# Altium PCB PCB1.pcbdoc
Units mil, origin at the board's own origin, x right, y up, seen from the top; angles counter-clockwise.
Board outline 4595.5 x 2047.9 mil, 2 copper layers (Top Layer, Bottom Layer), stack 62.2 mil thick; 88 components, 69 nets, 319 pads, 425 vias.
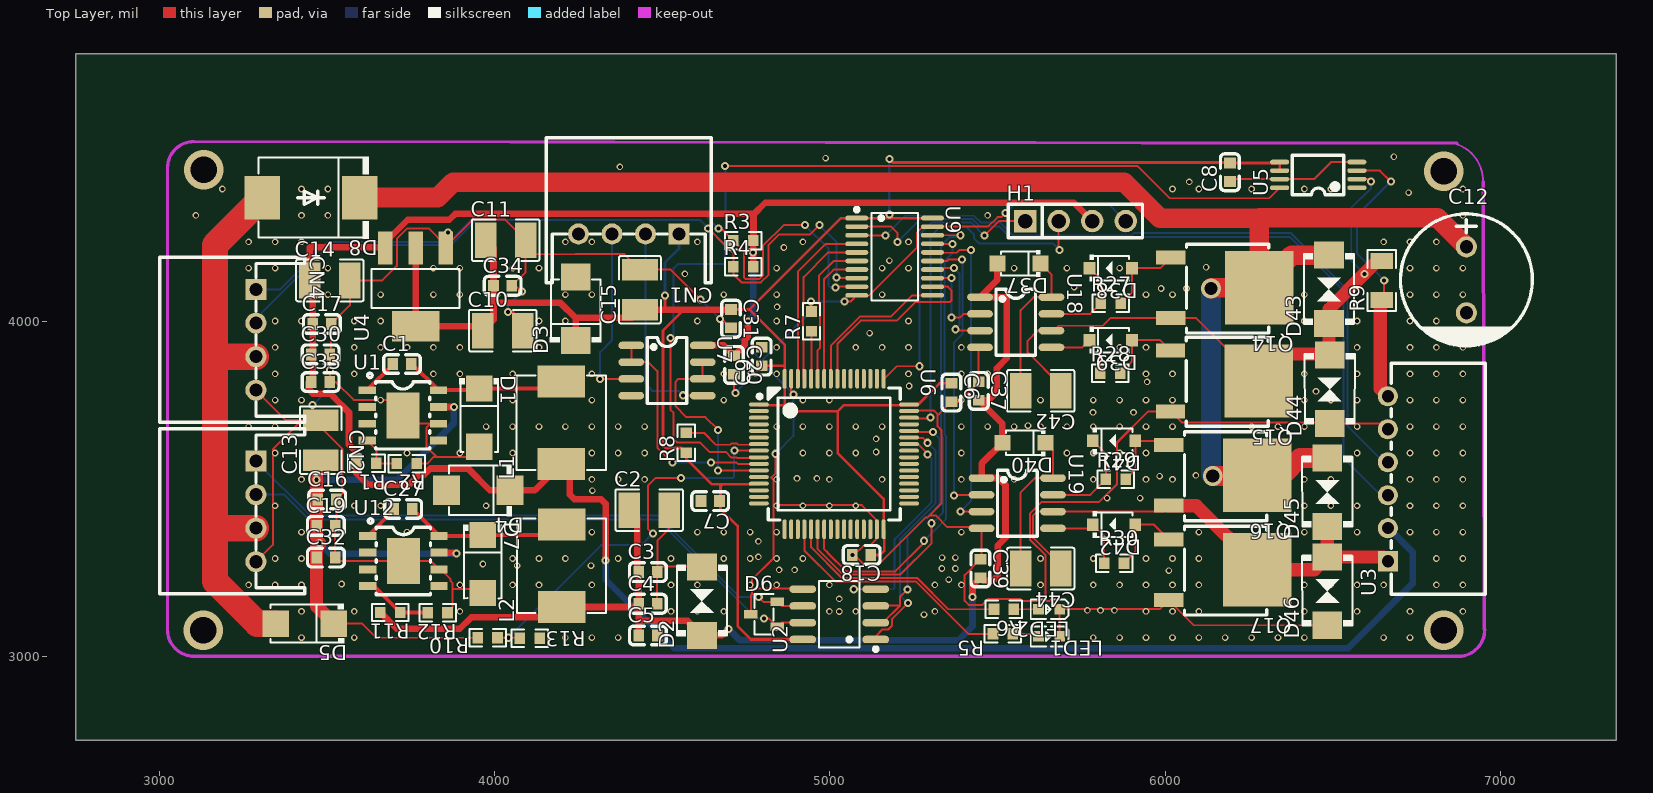
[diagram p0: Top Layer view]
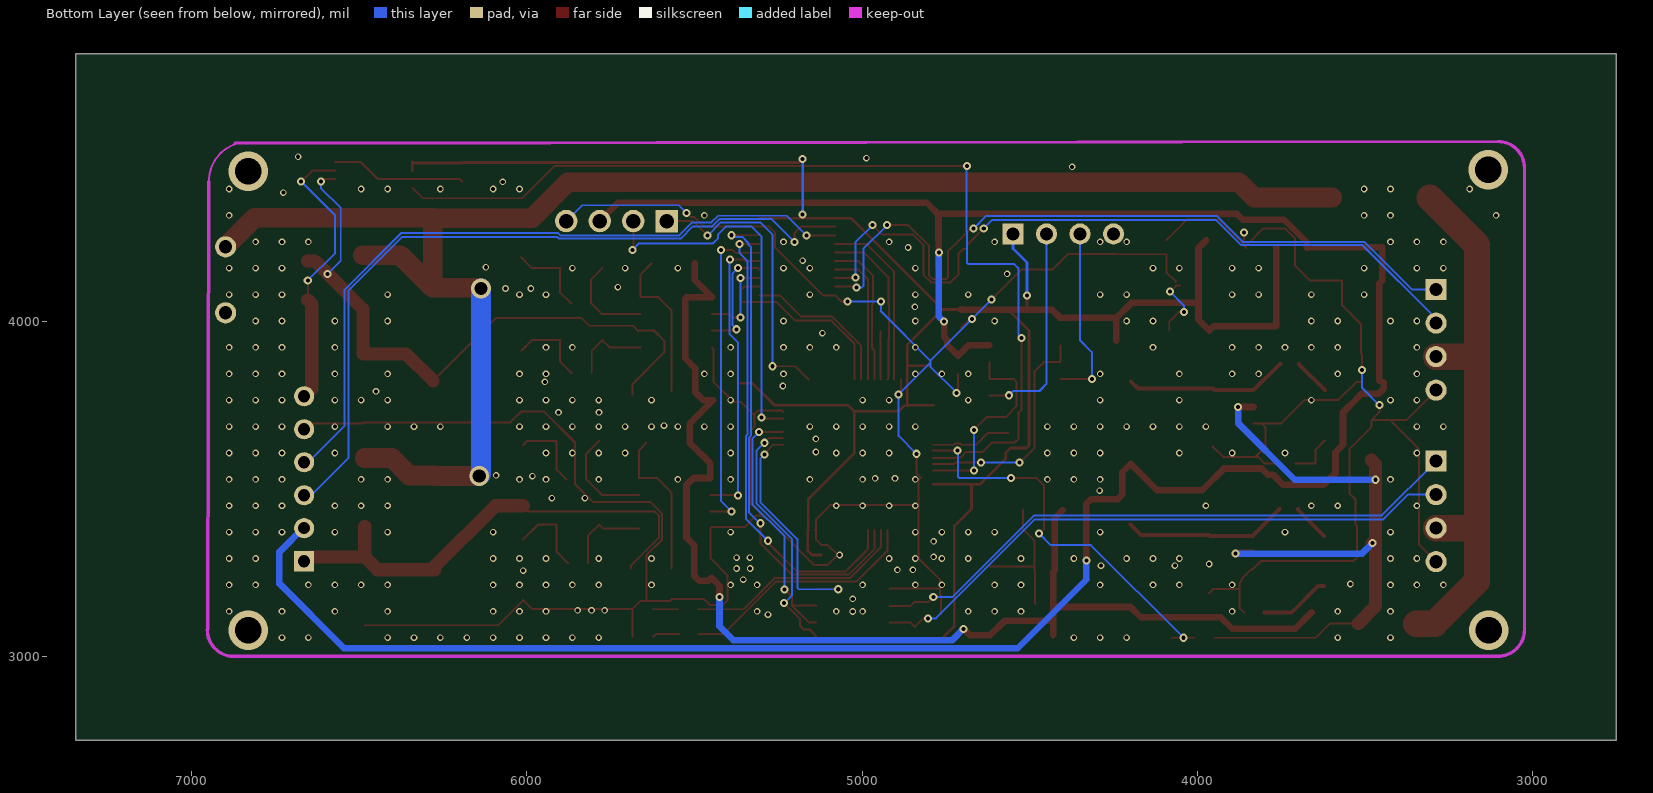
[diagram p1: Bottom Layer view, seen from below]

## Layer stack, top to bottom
Top Solder Mask Layer: solder mask 0.4, Dk 3.3
Top Layer: signal copper 1.4
Dielectric1: surface 59.4, FR4, Dk 4.5
Bottom Layer: signal copper 1.4
Bottom Solder Mask Layer: solder mask 0.4, Dk 3.3

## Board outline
7345.5,2750 2750,2750 2750,4797.9 7345.5,4797.9

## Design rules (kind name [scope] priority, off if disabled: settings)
BoardOutlineClearance copperThickness1oz [All] p0: genericclearance=10 ignorepadtopadclearanceinfootprint=FALSE except(0: Arc-SplitContinuation Track-SplitContinuation SMDPad-SplitContinuation THPad-SplitContinuation Via-SplitContinuation Fill-SplitContinuation Poly-SplitContinuation Region-SplitContinuation Text-SplitContinuation)
BoardOutlineClearance copperThickness2oz [All] p0: genericclearance=10 ignorepadtopadclearanceinfootprint=FALSE except(0: Arc-SplitContinuation Track-SplitContinuation SMDPad-SplitContinuation THPad-SplitContinuation Via-SplitContinuation Fill-SplitContinuation Poly-SplitContinuation Region-SplitContinuation Text-SplitContinuation)
BoardOutlineClearance otherClearance [All] p0: genericclearance=10 ignorepadtopadclearanceinfootprint=FALSE except(0: Arc-SplitContinuation Track-SplitContinuation SMDPad-SplitContinuation THPad-SplitContinuation Via-SplitContinuation Fill-SplitContinuation Poly-SplitContinuation Region-SplitContinuation Text-SplitContinuation)
Clearance copperThickness1oz [All] p1: gap=7 ignorepadtopadclearanceinfootprint=FALSE
Clearance copperThickness2oz [All] p1: gap=7 ignorepadtopadclearanceinfootprint=FALSE
Clearance otherClearance [All] p1: gap=7 ignorepadtopadclearanceinfootprint=FALSE
DiffPairsRouting differentialPair [All] p1: maxuncoupledlength=10 minlimit=6 maxlimit=Infinity mostfreqgap=6 toplayer_minwidth=5 toplayer_prefwidth=10 toplayer_maxwidth=100 bottomlayer_minwidth=5 bottomlayer_prefwidth=10 bottomlayer_maxwidth=100
PasteMaskExpansion pasteMaskExpansion [All] p1: expansion=0
PlaneConnect innerPlane [All] p1: planeconnectstyle=Direct reliefexpansion=20 reliefentries=4 reliefconductorwidth=10 reliefairgap=10
PolygonConnect copperRegion [All] p1: connectstyle=Direct reliefentries=4 reliefconductorwidth=10 polygonreliefangle="90 Angle" airgapwidth=10
RoutingVias viaSize [All] p1: viastyle="Through Hole" holewidth=12.0078 minholewidth=11.811 maxholewidth=248.0314 width=12.0078 minwidth=11.811 maxwidth=248.0314
SolderMaskExpansion solderMaskExpansion [IsVia] p1: useseparateexpansions=TRUE expansion=-1000 expansionbottom=-1000
SolderMaskExpansion solderMaskExpansion [All] p2: useseparateexpansions=TRUE expansion=2 expansionbottom=2
Width copperThickness1oz [All] p1: maxlimit=100 minlimit=5 preferedwidth=6
Width copperThickness2oz [All] p1: maxlimit=100 minlimit=8 preferedwidth=10
Width l24V [All] p1: maxlimit=100 minlimit=4 preferedwidth=39
Width i5V [All] p1: maxlimit=100 minlimit=5 preferedwidth=20
Width i3V [All] p1: maxlimit=100 minlimit=5 preferedwidth=8

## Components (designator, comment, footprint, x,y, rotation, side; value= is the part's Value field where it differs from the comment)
C1 "100nF" C0603#1 3723.3,3872.7 r0 top
C2 "10uF" C1210#1 4460.6,3436.7 r0 top
C3 "100nF" C0603#2 4456.7,3251.7 r0 top
C4 "100nF" C0603#2 4456.7,3157.2 r0 top
C5 "100nF" C0603#2 4456.7,3062.7 r0 top
C6 "100nF" C0603#1 5362.2,3787.1 r270 top
C7 "100nF" C0603#3 4642.7,3463.3 r180 top
C8 "100nF" C0603#3 6192.9,4444.6 r90 top
C9 "100nF" C0603#3 4796.3,3894.4 r90 top
C10 "10uF" C1210#1 4023.6,3972.1 r0 top
C11 "10uF" C1210#2 4032.2,4242 r0 top
C12 "470uF" CAP-TH_BD10.0-P5.00-D0.6-FD 6898.6,4123.7 r270 top
C13 "10uF" C1210#3 3480.3,3645.4 r90 top
C14 "10uF" C1210#3 3507.9,4121.7 r0 top
C15 "10uF" C1210#3 4433.1,4094.2 r90 top
C16 "100nF" C0603#2 3500,3468.2 r0 top
C17 "100nF" C0603#3 3484.3,3991.8 r0 top
C18 "100nF" C0603#1 5094.5,3302.8 r180 top
C19 "100nF" C0603#3 3496.1,3389.4 r0 top
C20 "100nF" C0603#1 4713.6,3869.8 r270 top
C27 "100nF" C0603#3 3726.7,3440 r0 top
C30 "100nF" C0603#1 3480.3,3901.3 r0 top
C31 "100nF" C0603#1 4704.7,4007.6 r270 top
C32 "100nF" C0603#3 3496.1,3295 r0 top
C33 "100nF" C0603#1 3480.3,3818.6 r0 top
C34 "100nF" C0603#1 4023.6,4106 r0 top
C37 "100nF" C0603#3 5443.7,3792.3 r270 top
C39 "100nF" C0603#3 5448.7,3262.3 r270 top
C42 "10uF" C1210#3 5628.7,3792.3 r180 top
C44 "10uF" C1210#3 5628.7,3262.3 r180 top
CN1 "2.54-4P WZ-D" CONN-TH_2.54-4P-WZ-D 4399.6,4260.5 r180 top
CN2 "2.54-4P WZ-D" CONN-TH_2.54-4P-WZ-D 3287.4,3432.8 r270 top
CN4 "2.54-4P WZ-D" CONN-TH_2.54-4P-WZ-D 3287.4,3944.6 r270 top
D1 "B340A-E3/61T" SMA_L4.3-W2.6-LS5.2-RD 3953.3,3712.7 r270 top
D2 "SMBJ36CA" SMB_L4.6-W3.6-LS5.4-BI#1 4618.1,3165 r90 top
D3 "SMBJ5.0A" SMB_L4.6-W3.6-LS5.4-RD 4241.1,4037.1 r90 top
D4 "SMBJ5.0A" SMB_L4.6-W3.6-LS5.4-RD 3950.8,3495.7 r180 top
D5 "B340A-E3/61T" SMA_L4.3-W2.6-LS5.2-RD 3433.1,3098.1 r180 top
D6 "SM712" SOT-23-3_L2.9-W1.3-P1.90-LS2.4-BR 4803.1,3125.7 r0 top
D7 "B340A-E3/61T" SMA_L4.3-W2.6-LS5.2-RD 3964.4,3275.8 r270 top
D8 "B560C" SMC_L6.9-W5.9-LS7.9-RD 3451.8,4368.8 r180 top
D37 "FR107W" SOD-123FL_L2.7-W1.8-LS3.8-RD 5563.7,4172.3 r180 top
D38 "1N4148W" SOD-123_L2.7-W1.6-LS3.7-FD 5837.7,4158.4 r180 top
D39 "1N4148W" SOD-123_L2.7-W1.6-LS3.7-FD 5837.7,3943.4 r180 top
D40 "FR107W" SOD-123FL_L2.7-W1.8-LS3.8-RD 5578.7,3637.3 r180 top
D41 "1N4148W" SOD-123_L2.7-W1.6-LS3.7-FD 5847.7,3643.4 r180 top
D42 "1N4148W" SOD-123_L2.7-W1.6-LS3.7-FD 5847.7,3393.4 r180 top
D43 "SMBJ36CA" SMB_L4.6-W3.6-LS5.4-BI#2 6488.7,4095.1 r90 top
D44 "SMBJ36CA" SMB_L4.6-W3.6-LS5.4-BI#2 6490.7,3797.1 r90 top
D45 "SMBJ36CA" SMB_L4.6-W3.6-LS5.4-BI#2 6483.7,3490.1 r90 top
D46 "SMBJ36CA" SMB_L4.6-W3.6-LS5.4-BI#2 6483.7,3195.1 r90 top
H1 "PZ254V-11-04P" HDR-TH_4P-P2.54-V-M 5732.3,4298.9 r0 top
L1 "22uH" IND-SMD_L7.0-W6.6_FXL0630 4198.3,3697.7 r90 top
L2 "22uH" IND-SMD_L7.0-W6.6_FXL0630 4199.4,3270.8 r90 top
LED1 "" LED_0603 5651.6,3059.7 r180 top
LED2 "" LED_0603 5651.6,3140.8 r180 top
Q14 "CMD100N08A" TO-252-3_L6.5-W5.8-P4.58-LS9.5-BR#1 6148.7,4100.1 r180 top
Q15 "CMD100N08A" TO-252-3_L6.5-W5.8-P4.58-LS9.5-BR#1 6147.7,3822 r180 top
Q16 "CMD100N08A" TO-252-3_L6.5-W5.8-P4.58-LS9.5-BR#2 6142.7,3540.3 r180 top
Q17 "CMD100N08A" TO-252-3_L6.5-W5.8-P4.58-LS9.5-BR#2 6142.7,3258.5 r180 top
R1 "10K" R0603#1 3617.1,3576.5 r180 top
R2 "10K" R0603#2 3737.2,3575.5 r180 top
R3 "10K" R0603#1 4741.2,4240.8 r0 top
R4 "10K" R0603#1 4741.2,4163.1 r0 top
R5 "10K" R0603#3 5516,3067.5 r180 top
R6 "10K" R0603#1 5518.7,3140.8 r180 top
R7 "10kΩ" R0603#1 4944.9,3999.7 r90 top
R8 "10kΩ" R0603#1 4570.9,3637.5 r90 top
R9 "10mΩ" R1206 6645.7,4121.7 r90 top
R10 "10K" R0603#1 3978.3,3055.8 r180 top
R11 "10K" R0603#3 3688.4,3131.1 r180 top
R12 "10K" R0603#2 3829.4,3130.8 r180 top
R13 "10K" R0603#1 4104.3,3054.8 r180 top
R27 "10K" R0603#1 5837.7,4053.4 r0 top
R28 "10K" R0603#3 5835.9,3845.3 r0 top
R29 "10K" R0603#1 5852.7,3528.4 r0 top
R30 "10K" R0603#1 5847.7,3278.4 r0 top
U1 "TPS5430DDAR" ESOP-8_L4.9-W3.9-P1.27-LS6.0-TL-EP 3725.6,3719.3 r0 top
U2 "SP3485EEN(UMW)" SOP-8_L5.0-W4.0-P1.27-LS6.0-BL 5027.6,3125.7 r90 top
U3 "WAFER-XH254WZ-6A" CONN-TH_6P-P2.50_WAFER-XH254WZ-6A 6664.4,3530.2 r90 top
U4 "AMS1117-3.3" SOT-223-3_L6.5-W3.4-P2.30-LS7.0-BR 3763.8,4102 r90 top
U5 "INA240A1PWR" TSSOP-8_L4.4-W3.0-P0.65-LS6.4-BL 6456.7,4436.7 r90 top
U6 "STM32F103RCT6" LQFP-64_L10.0-W10.0-P0.50-LS12.0-BL 5011.8,3604 r270 top
U7 "LM258DR" SOIC-8_L5.0-W4.0-P1.27-LS6.0-BL 4513.8,3853 r270 top
U9 "74HC245PW,118" TSSOP-20_L6.5-W4.4-P0.65-LS6.4-BL 5192.9,4192.6 r270 top
U12 "TPS5430DDAR" ESOP-8_L4.9-W3.9-P1.27-LS6.0-TL-EP 3727.5,3284.8 r0 top
U18 "EG2104S" SOIC-8_L5.0-W4.0-P1.27-LS6.0-BL 5554.1,3996.9 r270 top
U19 "EG2104S" SOIC-8_L5.0-W4.0-P1.27-LS6.0-BL 5558.7,3457.3 r270 top

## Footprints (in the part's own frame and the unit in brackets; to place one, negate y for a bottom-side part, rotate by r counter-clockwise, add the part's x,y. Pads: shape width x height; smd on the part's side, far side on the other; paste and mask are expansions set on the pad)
C0603#1 [mil]
  rect 31.5x35.4 smd: 1(-27.5,0) 2(27.6,0)
  silkscreen extent -55,-28 55,28
C0603#2 [mil]
  rect 31.5x35.4 smd: 1(-27.6,0) 2(27.6,0)
  silkscreen extent -55,-28 55,28
C0603#3 [mil]
  rect 31.5x35.4 smd: 1(-27.6,0) 2(27.5,0)
  silkscreen extent -55,-28 55,28
C1210#1 [mil]
  rect 64.4x106.3 smd paste-3937 mask+2: 1(-59.7,0) 2(59.8,0)
  silkscreen extent -101,-62 101,62
C1210#2 [mil]
  rect 64.4x106.3 smd paste-3937 mask+2: 1(-59.7,0) 2(59.7,0)
  silkscreen extent -101,-62 101,62
C1210#3 [mil]
  rect 64.4x106.3 smd paste-3937 mask+2: 1(-59.8,0) 2(59.7,0)
  silkscreen extent -101,-62 101,62
CAP-TH_BD10.0-P5.00-D0.6-FD [mil]
  round 63 hole 39.4 paste+0 mask+2: 1(-98.4,0) 2(98.4,0)
  silkscreen extent -197,-197 200,197
CONN-TH_2.54-4P-WZ-D [mil]
  rect 63x63 hole 39.4 paste+0 mask+2: 1(-150,0)
  round 63 hole 39.4 paste+0 mask+2: 2(-50,0) 3(50,0) 4(150,0)
  silkscreen extent -246,-287 246,146
CONN-TH_6P-P2.50_WAFER-XH254WZ-6A [mil]
  rect 60x60 hole 36: 1(-246.1,0)
  round 60 hole 36: 2(-147.6,0) 3(-49.2,0) 4(49.2,0) 5(147.6,0) 6(246.1,0)
  silkscreen extent -345,-290 345,-10
ESOP-8_L4.9-W3.9-P1.27-LS6.0-TL-EP [mm]
  rect 1.3x0.599 smd: 1(-2.7,1.905) 2(-2.7,0.635) 3(-2.7,-0.635) 4(-2.7,-1.905) 5(2.7,-1.905) 6(2.7,-0.635) 7(2.7,0.635) 8(2.7,1.905)
  rect 2.499x3.5 smd: 9(0,0)
  silkscreen extent -2.67,-2.55 2.05,3.2
HDR-TH_4P-P2.54-V-M [mil]
  rect 66.9x66.9 hole 43.3: 1(-150,0)
  round 66.9 hole 43.3: 2(-50,0) 3(50,0) 4(150,0)
  silkscreen extent -200,-50 200,50
IND-SMD_L7.0-W6.6_FXL0630 [mil]
  rect 95.4x142.5 smd: 1(123.1,0) 2(-123.2,0)
  silkscreen extent -141,-133 141,133
LED_0603 [mil]
  rect 31.5x31.5 smd paste+0 mask+2: 1(-33.5,-0.4) 2(29.5,-0.2)
  silkscreen extent -61,-30 53,30
LQFP-64_L10.0-W10.0-P0.50-LS12.0-BL [mil]
  oval 11.8x59.1 smd: 1(-147.7,-223.9) 2(-128,-223.9) 3(-108.3,-223.9) 4(-88.6,-223.9) 5(-68.9,-223.9) 6(-49.2,-223.9) 7(-29.5,-223.9) 8(-9.9,-223.9) 9(9.8,-223.9) 10(29.5,-223.9) 11(49.2,-223.9) 12(68.9,-223.9) 13(88.6,-223.9) 14(108.3,-223.9) 15(127.9,-223.9) 16(147.6,-223.9) 33(147.6,224) 34(127.9,224) 35(108.3,224) 36(88.6,224) 37(68.9,224) 38(49.2,224) 39(29.5,224) 40(9.8,224) 41(-9.9,224) 42(-29.5,224) 43(-49.2,224) 44(-68.9,224) 45(-88.6,224) 46(-108.3,224) 47(-128,224) 48(-147.7,224)
  oval 59.1x11.8 smd: 17(224.4,-147.2) 18(224.4,-127.5) 19(224.4,-107.8) 20(224.4,-88.1) 21(224.4,-68.4) 22(224.4,-48.7) 23(224.4,-29.1) 24(224.4,-9.4) 25(224.4,10.3) 26(224.4,30) 27(224.4,49.7) 28(224.4,69.4) 29(224.4,89.1) 30(224.4,108.7) 31(224.4,128.4) 32(224.4,148.1) 49(-224.4,148.1) 50(-224.4,128.4) 51(-224.4,108.7) 52(-224.4,89.1) 53(-224.4,69.4) 54(-224.4,49.7) 55(-224.4,30) 56(-224.4,10.3) 57(-224.4,-9.4) 58(-224.4,-29.1) 59(-224.4,-48.7) 60(-224.4,-68.4) 61(-224.4,-88.1) 62(-224.4,-107.8) 63(-224.4,-127.5) 64(-224.4,-147.2)
  silkscreen extent -197,-228 197,197
R0603#1 [mil]
  rect 31.8x34 smd paste-3937 mask+2: 1(-29.7,0) 2(29.6,0)
  silkscreen extent -55,-26 54,26
R0603#2 [mil]
  rect 31.8x34 smd paste-3937 mask+2: 1(-29.7,0) 2(29.7,0)
  silkscreen extent -54,-26 54,26
R0603#3 [mil]
  rect 31.8x34 smd paste-3937 mask+2: 1(-29.6,0) 2(29.7,0)
  silkscreen extent -54,-26 55,26
R1206 [mil]
  rect 47.5x67 smd paste-3937 mask+2: 1(-58.2,0) 2(58.3,0)
  silkscreen extent -91,-43 91,43
SMA_L4.3-W2.6-LS5.2-RD [mil]
  rect 78.7x78.7 smd: 1(-86.6,0) 2(86.6,0)
  silkscreen extent -117,-59 102,59
SMB_L4.6-W3.6-LS5.4-BI#1 [mil]
  rect 80.6x88.2 smd: 1(-102,0) 2(102.1,0)
  silkscreen extent -105,-75 108,75
SMB_L4.6-W3.6-LS5.4-BI#2 [mil]
  rect 80.6x88.2 smd: 1(-102,0) 2(102,0)
  silkscreen extent -105,-75 108,75
SMB_L4.6-W3.6-LS5.4-RD [mil]
  rect 80.6x88.2 smd: 1(-95,0) 2(95,0)
  silkscreen extent -100,-77 88,77
SMC_L6.9-W5.9-LS7.9-RD [mil]
  rect 106.3x129.9 smd: 1(-145.1,0) 2(145.2,0)
  silkscreen extent -172,-122 157,122
SOD-123_L2.7-W1.6-LS3.7-FD [mil]
  rect 34.6x37.8 smd: 1(-63.4,0) 2(63.4,0)
  silkscreen extent -54,-39 63,40
SOD-123FL_L2.7-W1.8-LS3.8-RD [mil]
  rect 47.2x47.2 smd: 1(-64.4,0) 2(64.3,0)
  silkscreen extent -63,-40 54,39
SOIC-8_L5.0-W4.0-P1.27-LS6.0-BL [mil]
  oval 22.4x76.8 smd: 1(-75,-106.5) 2(-25,-106.5) 3(25,-106.5) 4(75,-106.5) 5(75,106.5) 6(25,106.5) 7(-25,106.5) 8(-75,106.5)
  silkscreen extent -99,-59 98,59
SOP-8_L5.0-W4.0-P1.27-LS6.0-BL [mil]
  oval 22.6x80.1 smd: 1(-75,-108.9) 2(-25,-108.9) 3(25,-108.9) 4(75,-108.9) 5(75,109) 6(25,109) 7(-25,109) 8(-75,109)
  silkscreen extent -110,-115 99,60
SOT-23-3_L2.9-W1.3-P1.90-LS2.4-BR [mil]
  rect 39.4x25.6 smd: 1(39.4,-37.4) 2(39.4,37.4) 3(-39.3,0)
  silkscreen extent -28,-60 29,60
SOT-223-3_L6.5-W3.4-P2.30-LS7.0-BR [mil]
  rect 98.4x43.3 smd: 1(117,-90.5) 2(117,0) 3(117,90.6)
  rect 92.1x141.7 smd: 4(-116.9,0)
  silkscreen extent -62,-131 54,131
TO-252-3_L6.5-W5.8-P4.58-LS9.5-BR#1 [mil]
  rect 87.3x41.9 smd: 1(131.8,-90.5) 3(131.8,90.6)
  rect 204.9x218.6 smd: 2(-131.9,0)
  silkscreen extent -160,-130 85,135
TO-252-3_L6.5-W5.8-P4.58-LS9.5-BR#2 [mil]
  rect 87.3x41.9 smd: 1(131.8,-90.6) 3(131.8,90.5)
  rect 204.9x218.6 smd: 2(-131.9,0)
  silkscreen extent -160,-130 85,135
TSSOP-8_L4.4-W3.0-P0.65-LS6.4-BL [mil]
  oval 13.9x57.2 smd: 1(-38.4,-115.2) 2(-12.8,-115.2) 3(12.8,-115.2) 4(38.4,-115.2) 5(38.4,115.2) 6(12.8,115.2) 7(-12.8,115.2) 8(-38.4,115.2)
  silkscreen extent -59,-76 59,77
TSSOP-20_L6.5-W4.4-P0.65-LS6.4-BL [mil]
  oval 14.3x68.6 smd: 1(-115.2,-113) 2(-89.6,-113) 3(-64,-113) 4(-38.4,-113) 5(-12.8,-113) 6(12.8,-113) 7(38.4,-113) 8(64,-113) 9(89.6,-113) 10(115.2,-113) 11(115.2,113) 12(89.6,113) 13(64,113) 14(38.4,113) 15(12.8,113) 16(-12.8,113) 17(-38.4,113) 18(-64,113) 19(-89.6,113) 20(-115.2,113)
  silkscreen extent -146,-119 131,70

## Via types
v1: diameter 19.7, hole 11.8, Top Layer to Bottom Layer, 296 vias
v2: diameter 24, hole 12, Top Layer to Bottom Layer, 73 vias
v3: diameter 19.7, hole 12, Top Layer to Bottom Layer, 50 vias
v4: diameter 118.1, hole 78.7, Top Layer to Bottom Layer, 4 vias
v5: diameter 59.1, hole 39.4, Top Layer to Bottom Layer, 2 vias

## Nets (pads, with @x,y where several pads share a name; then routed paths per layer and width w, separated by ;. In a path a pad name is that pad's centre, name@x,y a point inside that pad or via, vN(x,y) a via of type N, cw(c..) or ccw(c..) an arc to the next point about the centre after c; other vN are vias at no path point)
3.3V: C6.1 C7.1 C8.2 C9.1 C10.1 C11.1 C15.1 C18.1 C31.1 C34.1 CN1.1 D3.1 R8.1 U2.8 U4.2 U4.4 U5.5 U5.6 U6.1 U6.13 U6.32 U6.48 U6.64 U9.1 U9.20 | length 6839.1
  Top Layer w7.9: 4506.7,4034.4 4507.9,4035.7 v2(4507.9,4077.4) ; 4564,4034.4 4502,3972.4 4502,3629.6 4509.8,3621.7 4557,3621.7 R8.1 4570.9,3590.2 4647.6,3513.5 4679.1,3513.5 ; C31.1 4759.8,4035.1 ; U6.13@4787.9,3513.5 4679.1,3513.5 ; U6.1@4787.9,3749.7 4863.1,3749.7 4864.6,3748.2 ; C9.1 4863.1,3866.8 4864.6,3868.4 ; U2.8 4764,3050.7 4724.4,3090.2 4724.4,3389.4 4673.2,3440.6 4673.2,3507.6 4679.1,3513.5 ; C18.1 5149.6,3302.8 5161.4,3314.6 5161.4,3376.1 5159.9,3377.6 5159.9,3469.7 5023.6,3606 5023.6,3732 ; v2(5177.2,4318.6) 5188,4307.8 ; v2(5177.2,4483.5) 5187.2,4473.5 6191.6,4473.5 C8.2 6338.5,4472.1 U5.5 U5.6 ; U9.20 5188,4307.8 ; C6.1 5326.8,3814.6 5261.8,3749.7 5235.8,3749.7 5041.3,3749.7 5023.6,3732 ; 4759.8,4035.1 5032.5,4307.8 U9.1 5188,4307.8 ; 4759.8,4035.1 4864.6,3930.3 4864.6,3868.4 ; 4864.6,3748.2 4865.1,3747.7 4874,3747.7 4889.8,3732 5023.6,3732 ; 4864.6,3748.2 U6.64 4864.6,3868.4
  Top Layer w19.7: U4.2 U4.4 3950.9,3985.1 C10.1 3996.1,4004.3 3996.1,4059.4 ; C11.1 3996.1,4218.4 C34.1 3996.1,4059.4 ; D3.1 4241.1,4010 ; C31.1 4704,4034.4 4564,4034.4 4506.7,4034.4 C15.1 4409.6,4011 4240.2,4011 4196.3,4054.8 4000.7,4054.8 3996.1,4059.4
  Bottom Layer w7.9: v2(4507.9,4077.4) 4507.9,4174.9 4549.6,4216.6 CN1.1 ; v2(5177.2,4318.6) v2(5177.2,4483.5)
12V: C2.1 C3.1 C4.1 C5.1 C37.2 C39.2 D2.1 D37.2 D40.2 L2.2 R11.2 U18.1 U19.1 | length 3686
  Top Layer w19.7: R11.2 3707.5,3082.4 3895.7,3082.4 3930.1,3116.8 4168.6,3116.8 L2.2 4419.6,3147.6 C4.1 ; C2.1 4425.2,3412.4 4425.2,3255.6 C3.1 C4.1 ; C5.1 4429.1,3114.6 ; v2(4696.8,3082.4) 4677.5,3063 D2.1 4575.1,3106 4437.8,3106 4429.1,3114.6 ; v2(5425.2,3176.9) 5425.2,3211.2 C39.2 5457.6,3225.9 5486.1,3225.9 5500,3239.8 5500,3330.4 5523.6,3354 5523.6,3511.5 5502.8,3532.3 U19.1 5452.2,3575.2 D40.2 5514.4,3694.1 C37.2 5473.7,3764.8 5498,3789.1 5498,3859.9 5527.6,3889.4 5527.6,4066.6 5522.2,4071.9 U18.1 5499.4,4123.7 D37.2 ; 4429.1,3114.6 C4.1
  Bottom Layer w19.7: v2(4696.8,3082.4) 4730.3,3048.9 5383.9,3048.9 5425.2,3090.2 v2(5425.2,3176.9)
24V: C13.1 C16.1 C19.1 C32.1 D5.1 R10.2 U1.7 U12.7 | length 2012.1
  Top Layer w5.9: D5.1 3604.3,3098.1 3646.7,3055.8 R10.2
  Top Layer w19.7: U1.7 3877.5,3744.3 v2(3878,3743.8) ; U12.7 3882.8,3309.8 v2(3885.8,3306.8)
  Top Layer w39.4: v2(3476.4,3338.3) v2@3478.5,3336.1 ; C13.1 3468.5,3573.8 v2(3468.5,3527.2) C19.1 C32.1 3468.5,3149.3 D5.1
  Bottom Layer w19.7: v2(3468.5,3527.2) 3708.7,3527.2 3878,3696.5 v2(3878,3743.8) ; v2(3476.4,3338.3) 3507.9,3306.8 v2(3885.8,3306.8)
24V-M: C12.1 D8.1 D43.2 D45.2 Q14.2 Q16.2 | length 4928.3
  Top Layer w59.1: D8.1 3829.7,4368.8 3876,4415 5877,4415 5984.9,4307.1 6280.6,4307.1 ; v5(6136.8,4098.1) 6138.8,4100.1 Q14.2 ; v5(6141.7,3538.1) 6272.3,3538.1 Q16.2 6350.7,3540.3 6402.5,3592.1 D45.2 ; D43.2 6377.6,4197.1 Q14.2 ; C12.1 6812,4308.7 6282.2,4308.7 6280.6,4307.1 ; Q14.2 6280.6,4307.1
  Bottom Layer w59.1: v5(6136.8,4098.1) 6136.8,3543 v5(6141.7,3538.1)
24V-P: CN2.3 CN4.3 D5.2 D8.2 | length 1681.6
  Top Layer w78.7: CN2.3 3287.2,3382.6 3165.1,3382.6 ; CN4.3 3165.1,3894.6 ; D8.2 3165.1,4227.2 3165.1,3894.6 ; D5.2 3291.1,3098.1 3165.1,3224.1 3165.1,3382.6 ; 3165.1,3382.6 3165.1,3894.6
$1N1: C1.1 U1.1 | length 110.1
  Top Layer w11.8: U1.1 3695.8,3870.7 C1.1
$1N2: C27.1 U12.1 | length 112.5
  Top Layer w11.8: U12.1 3699.1,3437.7 C27.1
$1N3: C1.2 D1.1 L1.1 U1.8 | length 490.9
  Top Layer w11.8: C1.2 3753.5,3872.7 U1.8 3948.3,3794.3 D1.1 4176.8,3799.3 L1.1
$1N4: C27.2 D7.1 L2.1 U12.8 | length 492.9
  Top Layer w11.8: C27.2 3833.8,3360.4 U12.8 3961.8,3359.8 D7.1 4167.9,3362.4 L2.1
$1N7: R1.1 R2.2 U1.4 | length 140.3
  Top Layer w5.9: U1.4 3646.8,3616.8 R1.1 3647.8,3575.5 R2.2
$1N8: R11.1 R12.2 U12.4 | length 211.3
  Top Layer w11.8: U12.4 3639.4,3209.8 R11.1 3799.4,3131.1 R12.2
$1N71: U6.57 U9.11 | length 464.5
  Top Layer w5.9: U6.57 5002.4,3927.3 5089.6,4014.4 5182.1,4014.4 5245.1,4077.4 U9.11
$1N72: U6.58 U9.7 | length 408.4
  Top Layer w5.9: U6.58@4982.7,3826.5 4982.7,4126.1 5010.8,4154.2 U9.7
$1N73: U6.59 U9.6 | length 444.4
  Top Layer w5.9: U6.59@4963.1,3826.5 4963.1,3913.5 4970.8,3921.3 4970.8,4048.9 4967.9,4051.8 4967.9,4136.6 5011.1,4179.8 U9.6
$1N74: U6.61 U9.5 | length 497.5
  Top Layer w5.9: U6.61@4923.7,3826.5 4921.3,3828.9 4921.3,3948.1 4918.9,3950.4 4918.9,4048.9 4921.3,4051.2 4921.3,4131.8 4994.8,4205.4 U9.5
$1N75: U6.62 U9.4 | length 532
  Top Layer w5.9: U6.62@4904,3826.5 4904,4148.3 4986.7,4231 U9.4
$1N90: C44.2 D40.1 U19.8 | length 455.5
  Top Layer w5.9: C44.2 5569,3489.9 5611.4,3532.3 U19.8 5665.2,3615.2 D40.1
$1N92: H1.1 U6.49 | length 881.4
  Top Layer w5.9: U6.49@5159.9,3826.5 5199.3,3865.8 v2(5267.7,3865.8) ; v2(5460.6,4255.6) 5503.9,4298.9 H1.1
  Bottom Layer w5.9: v2(5267.7,3865.8) 5267.7,4259.5 5303.1,4295 5421.3,4295 v2(5460.6,4255.6)
$1N93: H1.2 U6.46 | length 1126.4
  Top Layer w5.9: U6.46@5235.8,3710.3 5297.2,3710.3 v2(5299.2,3712.3) ; H1.2 5682.3,4215 v2(5685,4212.3)
  Bottom Layer w5.9: v2(5299.2,3712.3) 5299.2,4251.7 5330.7,4283.1 5405.5,4283.1 5429.1,4259.5 5429.1,4247.7 5444.9,4232 5665.4,4232 v2(5685,4212.3)
$1N120: D38.1 Q14.1 R27.2 | length 248.2
  Top Layer w5.9: R27.2 5901.1,4087.1 D38.1 5984.7,4158.4 Q14.1
$1N121: D41.1 Q16.1 R29.2 | length 231.9
  Top Layer w5.9: R29.2 5911.1,3557.1 D41.1 5998.4,3643.4 Q16.1
$1N122: D42.1 Q17.1 R30.2 | length 247.2
  Top Layer w5.9: R30.2 5911.1,3312.1 D42.1 5966.6,3393.4 Q17.1
$1N123: D39.1 Q15.1 R28.2 | length 240.4
  Top Layer w5.9: R28.2 5901.1,3880.8 D39.1 5985.1,3943.4 Q15.1
$1N124: D38.2 R27.1 U18.7 | length 279.4
  Top Layer w5.9: U18.7 5776.6,4021.9 R27.1 5808,4124.7 D38.2
$1N125: D39.2 R28.1 U18.5 | length 234
  Top Layer w5.9: U18.5 5752.8,3921.9 D39.2 5806.3,3911.4 R28.1
$1N126: D41.2 R29.1 U19.7 | length 308
  Top Layer w5.9: U19.7 5777,3482.3 R29.1 5823,3604.7 D41.2
$1N127: D42.2 R30.1 U19.5 | length 252.7
  Top Layer w5.9: U19.5 5773.2,3382.3 D42.2 5818,3359.7 R30.1
$1N128: C42.2 D37.1 U18.8 | length 462.4
  Top Layer w5.9: C42.2 5569,4033.3 5607.7,4071.9 U18.8 5660.6,4139.8 D37.1
$1N138: R8.2 U6.7 | length 242.1
  Top Layer w5.9: R8.2@4563,3666.9 4624.1,3666.9 4659.4,3631.6 4702.7,3631.6 4705.9,3634.8 4723.2,3634.8 4726.5,3631.6 U6.7@4787.9,3631.6
$1N139: R7.1 U6.60 | length 144.1
  Top Layer w5.9: U6.60@4943.4,3826.5 4944.9,3828 R7.1
$1N154: U6.30
$1N155: U6.29
$1N156: U6.28
$1N157: U6.27
$1N158: U6.26
$1N159: R6.2 U6.21 | length 674.2
  Top Layer w5.9: U6.21@4943.4,3377.6 4943.4,3325.7 5035.1,3234 5260,3234 5353.2,3140.8 R6.2
$1N160: R5.2 U6.20 | length 727.1
  Top Layer w5.9: U6.20@4923.7,3377.6 4923.7,3316.1 5015.7,3224.1 5255.9,3224.1 5412.5,3067.5 R5.2
$1N223: LED1.2 R5.1 | length 79.6
  Top Layer w5.9: R5.1 5614.4,3067.5 LED1.2
$1N227: LED2.2 R6.1 | length 73.8
  Top Layer w5.9: R6.1 5621.9,3140.8 LED2.2
$1N253: U6.17
$1N261: U6.56 U9.12 | length 589.1
  Top Layer w5.9: U6.56 5022.1,3932.2 5091.5,4001.7 5199.8,4001.7 5255.9,4057.8 5358.3,4057.8 5362.4,4061.9 5362.4,4092.2 5351.6,4103 U9.12
$1N270: CN1.3 U7.3 | length 541.4
  Top Layer w5.9: v2(4314,3827.4) 4406.7,3827.4 U7.3
  Bottom Layer w5.9: v2(4314,3827.4) 4314,3908.1 4349.6,3943.8 CN1.3
$1N271: CN1.2 U7.5 | length 632.8
  Top Layer w5.9: v2(4562,3779.2) 4619.1,3779.2 U7.5
  Bottom Layer w5.9: CN1.2 4449.6,3812.9 4470.5,3792 4549.2,3792 v2(4562,3779.2)
$1N277: R10.1 R13.2 U6.8 | length 1195.2
  Top Layer w5.9: R10.1 v2(4040.7,3055.8) 4073.7,3055.8 R13.2 ; v2(4471.5,3366.8) 4456.7,3381.6 4456.7,3509.8 4478.8,3531.9 v2(4556.1,3531.9) ; v2(4714.6,3613.9) U6.8
  Bottom Layer w5.9: v2(4040.7,3055.8) 4317.2,3332.4 4437,3332.4 v2(4471.5,3366.8) ; v2(4556.1,3531.9) 4709.4,3531.9 4713.6,3536.1 4713.6,3612.9 v2(4714.6,3613.9)
+5V: C14.1 C17.1 C20.1 C30.1 C33.1 D4.1 H1.3 L1.2 R1.2 R3.2 R4.2 U3.2 U4.3 U7.8 | length 7707.6
  Top Layer w19.7: C33.1@3443.8,3818.6 3443.8,3798.1 3457.7,3784.1 3508.9,3784.1 3543.4,3749.6 ; C33.1@3456.7,3822.5 C17.1 3456.7,4113.2 C14.1 3448.1,4220.3 3671.9,4220.3 U4.3 3673.2,4235.7 3740.4,4302.8 3864.2,4302.8 3882.3,4320.9 4769.3,4320.9 4771.7,4318.6 ; 3543.38,3749.63 cw(c3533.5,3737.3) 3545.83,3747.18 ; 3545.8,3747.2 3565,3728 3565,3631.6 3587.5,3609.1 R1.2 3587.5,3547.1 3622,3512.5 3744.1,3512.5 3774.3,3542.6 3789.3,3542.6 3807.4,3560.7 3920.3,3560.7 3985.2,3495.7 D4.1 4119.6,3495.7 L1.2 4223.4,3549.4 4223.4,3483 4237.3,3469 4316.9,3469 4330.8,3455.1 v2(4330.8,3286.1) ; U7.8 4682.9,3928 C20.1 4746.1,3929.8 4746.1,3944.6 4754.9,3953.4 v2(4754.9,3998.7) ; R4.2 v2(4770.8,4205.1) R3.2 4771.7,4241.6 4771.7,4318.6 ; H1.3 5727.6,4353.6 4806.6,4353.6 4771.7,4318.6
  Bottom Layer w19.7: v2(4330.8,3286.1) 4330.8,3228.9 4535.4,3024.3 6545.3,3024.3 6738.2,3217.2 6738.2,3311.7 U3.2@6661.4,3388.5 ; v2(4754.9,3998.7) 4770.8,4014.6 v2(4770.8,4205.1)
A: U6.22 U9.18 | length 1527.5
  Top Layer w5.9: U6.22@4963.1,3377.6 4963.1,3320.1 5039.2,3243.9 5208.8,3243.9 5303.1,3338.3 5303.1,3395.6 v2@5304,3396.5 ; U9.18 v2(5389.8,4256.6)
  Bottom Layer w5.9: v2@5304,3396.5 5336.7,3429.2 5336.7,3653.4 5330.7,3659.4 5330.7,4220.2 5338.6,4228 5338.6,4233.1 5357.5,4251.9 5385.1,4251.9 v2(5389.8,4256.6)
  other v2: 5303.1,3397.4
A485: CN2.1 D6.2 U2.6 | length 1810.2
  Top Layer w5.9: v2(4787.4,3176.9) 4801.2,3163.1 D6.2 4854.9,3150.7 U2.6
  Bottom Layer w5.9: CN2.1 3449.2,3420.9 4486.5,3420.9 4730.6,3176.9 v2(4787.4,3176.9)
ADC1_IN1_IA: U5.8 U6.9 | length 2951.9
  Top Layer w5.9: v2(4523.9,3949.4) 4523.9,3736.4 4533.8,3726.5 4533.8,3648.2 4543.5,3638.5 4611.8,3638.5 4640.2,3610.1 4688.7,3610.1 4705.9,3592.9 4721.5,3592.9 4722.2,3592.2 U6.9@4787.9,3592.2 ; v2(4686.4,4462.6) 5918.1,4462.6 6013.6,4367 6310.2,4367 U5.8
  Bottom Layer w5.9: v2(4523.9,3949.4) 4533.8,3959.3 4533.8,4158.2 4545.8,4170.3 4682.4,4170.3 4686.4,4174.3 4686.4,4266.7 4687.8,4268.1 4687.8,4461.1 v2(4686.4,4462.6)
ADC2: U6.10 U7.1 U7.2 | length 690.1
  Top Layer w5.9: U7.1 U7.2 4458.3,3878 4485.2,3851.1 4485.2,3622.7 v2(4529.5,3578.4) ; v2(4645.4,3578.4) 4721.5,3578.4 4725.4,3574.5 U6.10
  Bottom Layer w5.9: v2(4529.5,3578.4) v2(4645.4,3578.4)
ADC3: U6.11 U7.6 U7.7 | length 607.1
  Top Layer w5.9: U7.7 U7.6 4547.8,3828 4538.4,3818.6 4538.4,3747.7 4571.8,3714.3 4628,3714.3 v2(4666.3,3675.9) ; v2(4666.3,3554.8) U6.11
  Bottom Layer w5.9: v2(4666.3,3554.8) v2(4666.3,3675.9)
AO: U3.3 U9.2 | length 2255.4
  Top Layer w5.9: U9.2 5182.1,4282.2 5200.8,4263.5 v2(5200.8,4235.9)
  Bottom Layer w5.9: v2(5200.8,4235.9) 5269.8,4304.9 5425.4,4304.9 5447.1,4283.1 5504.4,4283.1 5541,4246.6 5904,4246.6 5909,4251.7 6372,4251.7 6531.5,4092.1 6531.5,3592.2 U3.3@6635.8,3487.9
B: U6.23 U9.17 | length 1410.3
  Top Layer w5.9: U6.23@4982.7,3377.6 4982.4,3377.3 4982.4,3320.4 4992.5,3310.3 4992.5,3309.8 5048.5,3253.9 5195.1,3253.9 5280.5,3339.2 v2(5280.5,3345.2) ; U9.17 v2(5366.1,4231)
  Bottom Layer w5.9: v2(5280.5,3345.2) 5346.6,3411.4 5346.6,3657.5 5341.3,3662.9 5341.3,4179.5 5366.1,4204.4 v2(5366.1,4231)
B485: CN2.2 D6.1 U2.7 | length 1799.8
  Top Layer w5.9: v2(4803.1,3113.9) 4816.9,3113.9 D6.1 4854.9,3100.7 U2.7
  Bottom Layer w5.9: CN2.2 3371.3,3482.8 3444.9,3409.1 4484.3,3409.1 4779.5,3113.9 v2(4803.1,3113.9)
BO: U3.4 U9.3 | length 2169.2
  Top Layer w5.9: U9.3 5080.9,4255.6 v2(5165.4,4255.6)
  Bottom Layer w5.9: v2(5165.4,4255.6) 5224.6,4314.8 5429.5,4314.8 5449.3,4295 5506.7,4295 5545.1,4256.5 5899.8,4256.5 5907.1,4263.7 6373.9,4263.7 6543.3,4094.3 6543.3,3688.7 6661.4,3570.6 U3.4@6661.4,3559.7
DE: U2.2 U2.3 U6.44 | length 812.7
  Top Layer w5.9: U2.2 5157.8,3100.7 5208.9,3151.8 ; U2.3 5137.6,3151.8 5208.9,3151.8 ; v2(5230.6,3199.5) 5208.9,3177.8 5208.9,3151.8 ; U6.44@5235.8,3670.9 5237.7,3669 v2(5307.1,3669)
  Bottom Layer w5.9: v2(5230.6,3199.5) 5230.6,3358 5326.8,3454.2 5326.8,3649.3 v2(5307.1,3669)
GND: C2.2 C3.2 C4.2 C5.2 C6.2 C7.2 C8.1 C9.2 C10.2 C11.2 C12.2 C13.2 C14.2 C15.2 C16.2 C17.2 C18.2 C19.2 C20.2 C30.2 C31.2 C32.2 C33.2 C34.2 C37.1 C39.1 CN1.4 CN2.4 CN4.4 D1.2 D2.2 D3.2 D4.2 D6.3 D7.2 D44.1 D46.1 H1.4 LED1.1 LED2.1 Q15.3 Q17.3 R2.1 R7.2 R12.1 R13.1 U1.6 U1.9 U2.5 U3.5 U4.1 U5.4 U5.7 U6.12 U6.31 U6.47 U6.63 U7.4 U9.10 U9.19 U12.6 U12.9 U18.4 U19.4 | length 12962.5
  Top Layer w5.9: CN2.4 3337.6,3333 3337.6,3618.5 3424.2,3705.1 ; CN4.4 3376.9,3705.1 3424.2,3705.1 ; v2(3456.7,3749.7) 3456.7,3728.7 C13.2 ; R2.1 3798.4,3575.5 3818.1,3595.3 3826,3595.3 ; U1.6 3830.5,3695.6 U1.6@3808.3,3695.6 ; U4.1 3862.2,4226.8 U4.1@3862.2,4230.8 ; U4.1@3855.7,4224.3 3802.9,4277.1 3738.4,4277.1 3708.1,4246.8 3708.1,4165.3 3664.5,4121.7 C14.2 3567.6,4047.6 C17.2 3511.8,3905.2 C30.2 v2(3507.9,3854) C33.2 3525.6,3818.6 3578.7,3765.4 3679.4,3765.4 U1.9 3749.2,3695.6 U1.6@3808.3,3695.6 ; R12.1 3874.2,3145.9 3874.2,3200.8 ; v2(3860.2,4264.4) 3860.2,4232.8 U4.1@3862.2,4230.8 ; D1.2 3922.5,3595.3 3826,3595.3 ; D7.2 3952.8,3200.8 3874.2,3200.8 ; v2(4039.4,4027) 4055.1,4027 4083.4,3998.7 C10.2 ; C34.2 4063,4106 v2(4080.7,4088.3) ; C34.2@4063,4117.8 4091.9,4146.7 4091.9,4199.9 4239.6,4199.9 ; C11.2 4029.8,4304.1 3935.5,4304.1 U4.1@3862.2,4230.8 ; 4240.2,4201 4240.2,4200.5 4386.5,4200.5 C15.2 4524.6,4153.9 v2(4613.2,4065.3) ; C4.2 C3.2 4484.9,3252.3 C3.2@4484.9,3268.4 ; C2.2 4520.4,3380.6 4484.9,3345.2 C3.2@4484.9,3268.4 ; D2.2 4616.8,3268.4 C3.2@4484.9,3268.4 ; v2(4672.2,4006.3) 4678.4,4006.3 C31.2 ; C20.2 4713.6,3790 v2(4717.5,3786.1) ; D6.3 4763.8,3182.5 4766.7,3185.4 4766.7,3203.1 ; v2(4837.6,3604.7) 4837.6,3546.9 4824.5,3533.8 4824.1,3533.8 4831.7,3526.3 v1@4831.7,3451.2 ; U6.63@4884.3,3826.5 4884.3,3788.3 v2(4890.7,3781.9) ; U2.5 4916.1,3203.1 4766.7,3203.1 ; v2(4943.3,4058.9) 4943.3,4030.9 R7.2 ; v2(5043.7,4058.9) 5061.3,4058.9 U9.10 5117.1,4077.4 5258.9,4219.2 5258.9,4264.6 5276.6,4282.3 U9.19@5305.8,4282.3 ; v3(5066.9,3302.8) C18.2@5072.8,3302.8 ; U6.31@5140.2,3377.6 U6.31@5137.8,3375.2 ; U6.47@5235.8,3730 5239.7,3733.9 5309.1,3733.9 5320.9,3722.1 ; U9.19 5471.3,4282.2 5499.8,4310.7 5511.6,4310.7 v2(5523.5,4322.5) ; U18.4 5443.7,3918 C37.1 5383.4,3759.5 C6.2 5324.8,3722.1 5320.9,3722.1 ; LED1.1 LED2.1 ; C8.1 6199.8,4423.9 U5.7 6443.9,4423.9 6495.1,4475.1 U5.4 ; D46.1 6085.8,3093.1 6010.9,3167.9 5984.2,3141.2 LED2.1 ; D44.1@6488.7,3698.1 6049.3,3698.1 Q15.3 5949.3,3731.4 5856.2,3638.3 5856.2,3514.3 5803.1,3461.1 5631.8,3461.1 5596.4,3425.7 5596.4,3348.9 5643.6,3301.7 5643.6,3165.9 ; D44.1 6647.1,3695.1 U3.5 ; 3424.2,3705.1 C13.2 ; C13.2 3480.3,3684.4 3546.2,3618.6 3546.2,3486.8 C16.2 3527.6,3393.4 C19.2 C32.2 3533.8,3284.8 U12.9 3808.8,3284.8 U12.6 3838.8,3259.8 3868.3,3230.3 3868.3,3224.4 3874.2,3218.5 3874.2,3200.8 ; U1.6@3808.3,3695.6 3796.5,3683.8 3796.5,3624.8 3826,3595.3 ; 4766.7,3203.1 4766.7,3228.7 4831.7,3293.7 v1@4831.7,3451.2 ; v1@4831.7,3451.2 5094.8,3451.2 5137.8,3408.1 U6.31@5137.8,3375.2 ; C18.2@5072.8,3302.8 5102.4,3332.4 5120.1,3332.4 5137.8,3350.1 U6.31@5137.8,3375.2 ; C18.2@5072.8,3302.8 5102.4,3273.3 5143.7,3273.3 5285.4,3415 5291.3,3415 5297.2,3420.9 ; 5297.2,3420.9 5315,3420.9 5350.4,3385.5 5449,3385.5 U19.4 5452.2,3293.4 C39.1 5401.5,3242.6 5401.5,3165.9 5413.3,3154.1 5454.6,3154.1 5472.4,3171.8 5566.8,3171.8 5572.8,3165.9 5643.6,3165.9 ; 5297.2,3420.9 5332.7,3456.4 5332.7,3674.9 5320.9,3686.7 5320.9,3722.1 ; 5643.6,3165.9 5660.4,3165.9 LED2.1
  Bottom Layer w5.9: v2(3456.7,3749.7) 3507.9,3800.9 v2(3507.9,3854) ; v2(4039.4,4027) 4039.4,4046.9 v2(4080.7,4088.3) ; v2(4613.2,4065.3) v2(4672.2,4006.3) 4796.3,3882.3 ; v2(4717.5,3786.1) 4796.3,3864.8 4796.3,3876.4 ; v2(4837.6,3604.7) 4890.7,3657.9 v2(4890.7,3781.9) 4796.3,3876.4 ; v2(5043.7,4058.9) v2(4943.3,4058.9) 4943.3,4029.3 4796.3,3882.3 ; v2(5523.5,4322.5) 5547.1,4346.1 5835,4346.1 H1.4 ; 4796.3,3876.4 4796.3,3882.3
  other v1: 3423.2,3055.9 3580.7,3055.9 4210.6,3055.9 4289.4,3055.9 4368.1,3055.9 5785.4,3055.9 5864.2,3055.9 5942.9,3055.9 6021.7,3055.9 6100.4,3055.9 6179.1,3055.9 6257.9,3055.9 6336.6,3055.9 6415.4,3055.9 6651.6,3055.9 6730.3,3055.9 3423.2,3134.7 3580.7,3134.7 3895.7,3134.7 4525.6,3134.7 4604.3,3134.7 4683.1,3134.7 4998,3134.7 5076.8,3134.7 5313,3134.7 5942.9,3134.7 6021.7,3134.7 6100.4,3134.7 6415.4,3134.7 6572.8,3134.7 6730.3,3134.7 6887.8,3134.7 3265.7,3213.4 3344.5,3213.4 3423.2,3213.4 3895.7,3213.4 4053.1,3213.4 4131.9,3213.4 4289.4,3213.4 4525.6,3213.4 4604.3,3213.4 4761.8,3213.4 4840.6,3213.4 4998,3213.4 5313,3213.4 5391.7,3213.4 5628,3213.4 5785.4,3213.4 5864.2,3213.4 5942.9,3213.4 6021.7,3213.4 6100.4,3213.4 6415.4,3213.4 6494.1,3213.4 6572.8,3213.4 6651.6,3213.4 6809.1,3213.4 6887.8,3213.4 3344.5,3292.1 3423.2,3292.1 4053.1,3292.1 4131.9,3292.1 4210.6,3292.1 4368.1,3292.1 4525.6,3292.1 4683.1,3292.1 4761.8,3292.1 4840.6,3292.1 4919.3,3292.1 5628,3292.1 5785.4,3292.1 5942.9,3292.1 6021.7,3292.1 6100.4,3292.1 6809.1,3292.1 6887.8,3292.1 3423.2,3370.9 3738.2,3370.9 4289.4,3370.9 4604.3,3370.9 4683.1,3370.9 4761.8,3370.9 4840.6,3370.9 5391.7,3370.9 6100.4,3370.9 6415.4,3370.9 6572.8,3370.9 6730.3,3370.9 6809.1,3370.9 6887.8,3370.9 3344.5,3449.6 3580.7,3449.6 3659.4,3449.6 3974.4,3449.6 4840.6,3449.6 4919.3,3449.6 4998,3449.6 5076.8,3449.6 6415.4,3449.6 6494.1,3449.6 6572.8,3449.6 6730.3,3449.6 6809.1,3449.6 6887.8,3449.6 3423.2,3528.4 4289.4,3528.4 4368.1,3528.4 4446.9,3528.4 4840.6,3528.4 4998,3528.4 5155.5,3528.4 5391.7,3528.4 5549.2,3528.4 5785.4,3528.4 5942.9,3528.4 6021.7,3528.4 6415.4,3528.4 6494.1,3528.4 6730.3,3528.4 6809.1,3528.4 6887.8,3528.4 3344.5,3607.1 3738.2,3607.1 3895.7,3607.1 4053.1,3607.1 4289.4,3607.1 4368.1,3607.1 4446.9,3607.1 4919.3,3607.1 4998,3607.1 5076.8,3607.1 5391.7,3607.1 5706.7,3607.1 5785.4,3607.1 5864.2,3607.1 5942.9,3607.1 6572.8,3607.1 6730.3,3607.1 6809.1,3607.1 6887.8,3607.1 3265.7,3685.8 3344.5,3685.8 3974.4,3685.8 4053.1,3685.8 4131.9,3685.8 4210.6,3685.8 4289.4,3685.8 4368.1,3685.8 4446.9,3685.8 4840.6,3685.8 4919.3,3685.8 4998,3685.8 5076.8,3685.8 5155.5,3685.8 5391.7,3685.8 5470.5,3685.8 5549.2,3685.8 5628,3685.8 5706.7,3685.8 5785.4,3685.8 5864.2,3685.8 5942.9,3685.8 6021.7,3685.8 6257.9,3685.8 6336.6,3685.8 6415.4,3685.8 6572.8,3685.8 6730.3,3685.8 6809.1,3685.8 6887.8,3685.8 3344.5,3764.6 3423.2,3764.6 3659.4,3764.6 4053.1,3764.6 4289.4,3764.6 4683.1,3764.6 4919.3,3764.6 4998,3764.6 5391.7,3764.6 5628,3764.6 5785.4,3764.6 5864.2,3764.6 5942.9,3764.6 6021.7,3764.6 6415.4,3764.6 6494.1,3764.6 6572.8,3764.6 6730.3,3764.6 6809.1,3764.6 6887.8,3764.6 3344.5,3843.3 3580.7,3843.3 3816.9,3843.3 3895.7,3843.3 4053.1,3843.3 4289.4,3843.3 4683.1,3843.3 4761.8,3843.3 4840.6,3843.3 5234.3,3843.3 5391.7,3843.3 5470.5,3843.3 5942.9,3843.3 6021.7,3843.3 6415.4,3843.3 6572.8,3843.3 6730.3,3843.3 6809.1,3843.3 6887.8,3843.3 3344.5,3922.1 3580.7,3922.1 3659.4,3922.1 3738.2,3922.1 3816.9,3922.1 3895.7,3922.1 4131.9,3922.1 4840.6,3922.1 5076.8,3922.1 5155.5,3922.1 5234.3,3922.1 5391.7,3922.1 5864.2,3922.1 5942.9,3922.1 6572.8,3922.1 6730.3,3922.1 6809.1,3922.1 6887.8,3922.1 3344.5,4000.8 3423.2,4000.8 3580.7,4000.8 3659.4,4000.8 4131.9,4000.8 4210.6,4000.8 4604.3,4000.8 4840.6,4000.8 5234.3,4000.8 6415.4,4000.8 6572.8,4000.8 6730.3,4000.8 6809.1,4000.8 3502,4079.5 3659.4,4079.5 3816.9,4079.5 3895.7,4079.5 4210.6,4079.5 4289.4,4079.5 4683.1,4079.5 4840.6,4079.5 5155.5,4079.5 5942.9,4079.5 6021.7,4079.5 6415.4,4079.5 6730.3,4079.5 6809.1,4079.5 6887.8,4079.5 3265.7,4158.3 3344.5,4158.3 3502,4158.3 3816.9,4158.3 3895.7,4158.3 4053.1,4158.3 4131.9,4158.3 4840.6,4158.3 5155.5,4158.3 5234.3,4158.3 5549.2,4158.3 5706.7,4158.3 5864.2,4158.3 6730.3,4158.3 6809.1,4158.3 6887.8,4158.3 3265.7,4237 3344.5,4237 3423.2,4237 4210.6,4237 4289.4,4237 4604.3,4237 4919.3,4237 5234.3,4237 6651.6,4237 6730.3,4237 6809.1,4237 3108.3,4315.8 3423.2,4315.8 3502,4315.8 5470.5,4315.8 6887.8,4315.8 3187,4394.5 3423.2,4394.5 3502,4394.5 6021.7,4394.5 6100.4,4394.5 6257.9,4394.5 6415.4,4394.5 6494.1,4394.5 6887.8,4394.5
  other v3: 5280.5,3124.7 5027.6,3134.2 5767.7,3137.5 5807.1,3137.5 5848.5,3137.5 5027.6,3172 3543.3,3216.2 5354.3,3229 6010.9,3256 4848.4,3258.5 4894.7,3258.5 5333.7,3262.3 5374,3262.3 4066.5,3270.8 4287.1,3270.8 3964.4,3275.8 5334.6,3295 5374,3295 4786.4,3296.9 4786.4,3343.2 5826.8,3472.1 5925.2,3472.1 4291.3,3494.7 4901.6,3531.2 4960.6,3531.2 5983.2,3537.8 6091.5,3540.3 5137.8,3609.9 5137.8,3649.3 5590.6,3688.7 5784.6,3728 5905.5,3728 6449.8,3791 5236.2,3806.8 5946.2,3819.5 5118.1,3964.3 4842.5,4043 5988.2,4097.6 6063.7,4097.6 5728.3,4102 4566.9,4141.4 6122,4161.1 5177.2,4180.8 4862.2,4220.2 6726.4,4383.5 6071.8,4416 4373,4460.4 4987.2,4486.9 6682.1,4490.8
IN1: CN4.2 R4.1 U9.8 | length 2296.2
  Top Layer w5.9: v2(4636.8,4277.2) 4686.7,4227.4 4686.7,4220.1 4691.9,4214.9 4699.2,4214.9 4711.5,4202.6 R4.1 4711.5,4140.3 4736,4115.7 4793.5,4115.7 4817,4139.3 4817,4227.9 4848.7,4259.5 4940.9,4259.5 v2(4968.5,4287.1) ; v2(5019.7,4130.8) 5021.9,4128.6 U9.8
  Bottom Layer w5.9: CN4.2 3287.4,4007.6 3506.8,4227 3868.3,4227 3944.1,4302.8 4611.2,4302.8 v2(4636.8,4277.2) ; v2(4968.5,4287.1) 5019.7,4235.9 v2(5019.7,4130.8)
IN2: CN4.1 R3.1 U9.9 | length 2269.7
  Top Layer w5.9: v2(4666.9,4276.8) 4675.5,4276.8 R3.1 4744.1,4208.2 4744.1,4129.8 4748.3,4125.7 4789.4,4125.7 4799.7,4136 4799.7,4224.6 4862.2,4287.1 v2(4925.2,4287.1) ; v2(5016.7,4100.8) 5018.9,4103 U9.9
  Bottom Layer w5.9: CN4.1 3358.7,4094.6 3501,4236.9 3864.2,4236.9 3941.9,4314.6 4629,4314.6 v2(4666.9,4276.8) ; v2(4925.2,4287.1) 4996.1,4216.2 4996.1,4105 5000.2,4100.8 v2(5016.7,4100.8)
key1: U6.15
key2: U6.16
M1A: R9.1 U3.6 U5.3 | length 845.7
  Top Layer w5.9: U5.3 6640.7,4449.5 v2(6673.2,4417) ; R9.1@6653.5,4063.5 v2(6653.5,4121.7)
  Top Layer w39.4: R9.1@6653.5,4063.5 6641.7,4051.7 6641.7,3798.9 U3.6
  Bottom Layer w5.9: v2(6653.5,4121.7) 6571.7,4203.5 6571.7,4315.5 v2(6673.2,4417)
M1B: C44.1 D45.1 D46.2 Q16.3 Q17.2 U3.1 U19.6 | length 1460.2
  Top Layer w5.9: C44.1 5688.5,3271.8 5606.3,3354 5606.3,3420.9 5617.7,3432.3 U19.6 5993.5,3432.3 Q16.3
  Top Layer w39.4: Q16.3 6093.2,3449.8 6274.6,3268.4 Q17.2 6445.1,3258.5 D46.2 ; D45.1 D46.2 ; U3.1 6651.4,3297.1 D46.2
PWMD1O: U9.13 U18.2 | length 263.1
  Top Layer w5.9: U9.13 v2(5362.2,4128.6) ; v2(5362.2,4011.5) 5388.6,4011.5 5399,4021.9 U18.2
  Bottom Layer w5.9: v2(5362.2,4011.5) v2(5362.2,4128.6)
PWMD2O: U9.15 U19.2 | length 889
  Top Layer w5.9: U9.15 5349.4,4179.8 5354.3,4184.7 v2(5393.7,4184.7) ; v2(5370.1,3480) 5372.4,3482.3 U19.2
  Bottom Layer w5.9: v2(5370.1,3480) 5370.1,3936.7 5395.7,3962.4 5395.7,4182.7 v2(5393.7,4184.7)
RX: U2.1 U6.43 | length 761.4
  Top Layer w5.9: U2.1 5136.5,3060.4 5156.5,3080.4 5173.7,3080.4 5185.5,3092.3 5185.5,3112.4 v2(5232.3,3159.1) ; U6.43@5235.8,3651.3 5277.6,3651.3 v2(5291.3,3637.5)
  Bottom Layer w5.9: v2(5232.3,3159.1) 5208.7,3182.8 5208.7,3350.1 5315,3456.4 5315,3613.9 v2(5291.3,3637.5)
SDD1O: U9.14 U18.3 | length 335.5
  Top Layer w5.9: U9.14 5310.4,4158.6 v2(5370.1,4158.6) ; v2@5373.8,3976.3 5378,3972.1 5447.4,3972.1 U18.3
  Bottom Layer w5.9: v2(5370.1,4158.6) 5385.8,4142.9 5385.8,3987.9 v2(5374,3976.1)
SDD2O: U9.16 U19.3 | length 974.3
  Top Layer w5.9: U9.16 5306.9,4204.4 5378,4204.4 5385.8,4212.3 v2(5421.3,4212.3) ; v2(5389.8,3432.8) 5451.8,3432.8 U19.3
  Bottom Layer w5.9: v2(5389.8,3432.8) 5421.3,3464.3 v2(5421.3,4212.3)
SHA: C42.1 D43.1 D44.2 Q14.3 Q15.2 R9.2 U5.2 U18.6 | length 1952.8
  Top Layer w5.9: U18.6@5662.7,3972.5 5620.6,3972.5 5589.4,3941.3 5589.4,3907.4 5684.7,3812 C42.1@5684.7,3780.9 ; U18.6@5667.2,3970.7 5683.1,3986.6 5813.9,3986.6 5836.5,4009.2 Q14.3@6015.6,4009.2 ; Q14.3 6092,4009.5 Q15.2 ; U5.2 6607.3,4423.9 v2(6614.2,4417)
  Top Layer w39.4: Q15.2 6359.7,3902.1 6488.7,3902.1 D43.1 6488.7,4035.7 v2(6594.5,4141.4) 6633,4180 R9.2@6653.5,4180
  Bottom Layer w5.9: v2(6594.5,4141.4) 6555.1,4180.8 6555.1,4338.3 6614.2,4397.3 v2(6614.2,4417)
TX: U2.4 U6.42 | length 707
  Top Layer w5.9: v2(5070.9,3200.5) 5136.3,3200.5 U2.4 ; U6.42@5235.8,3631.6 5264.8,3631.6 5291.3,3605 v2(5291.3,3602)
  Bottom Layer w5.9: v2(5070.9,3200.5) 5189,3200.5 5192.9,3204.4 5192.9,3350.1 5303.1,3460.3 5303.1,3590.2 v2(5291.3,3602)
pads on no net: U1.2 U1.3 U1.5 U5.1 U6.2 U6.3 U6.4 U6.5 U6.6 U6.14 U6.18 U6.19 U6.24 U6.25 U6.33 U6.34 U6.35 U6.36 U6.37 U6.38 U6.39 U6.40 U6.41 U6.45 U6.50 U6.51 U6.52 U6.53 U6.54 U6.55 U12.2 U12.3 U12.5
copper on no net:
  other v4: 3129.9,3078.4 6830.7,3078.4 6830.7,4447.4 3131.5,4452.1

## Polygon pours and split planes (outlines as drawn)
GND on Top Layer (solid, remove dead copper, pour order 2): 3012,4538.6 3012,3000 6949.1,3000 6949.1,4538.6
GND on Bottom Layer (solid, remove dead copper, pour order 2): 3012,4538.6 3012,3000 6949.1,3000 6949.1,4538.6

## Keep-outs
Board Outline Layer:
  lines w5.9: 6854.7,4532.7 6863.9,4530.3 6872.9,4527.3 6881.6,4523.6 6890,4519.1 6898.1,4514 6905.6,4508.3 6912.7,4502 6919.3,4495.1 6925.3,4487.8 6930.7,4479.9 6935.4,4471.7 6939.4,4463.1 6942.8,4454.2 6945.4,4445.1 6947.3,4435.8 6948.4,4426.4 6948.8,4416.9
  lines w10: 3023.6,3079.2 3024,3071.4 3025.2,3063.7 3027.2,3056.1 3029.9,3048.8 3033.3,3041.7 3037.4,3035.1 3042.1,3028.8 3047.4,3023.1 3053.3,3017.9 3059.6,3013.4 3066.4,3009.4 3073.5,3006.2 3080.9,3003.7 3088.5,3002 3096.3,3001 3104.1,3000.8 ; 3023.6,3079.5 3023.6,4457.4 ; 3023.6,4457.8 3024,4465.5 3025.2,4473.1 3027.1,4480.6 3029.7,4487.8 3033,4494.8 3037,4501.4 3041.6,4507.6 3046.8,4513.3 3052.5,4518.4 3058.7,4523 3065.3,4526.9 3072.3,4530.2 3079.6,4532.8 3087,4534.7 3094.7,4535.8 3102.4,4536.2 6870.3,4531.2 ; 3102.4,3000.7 6875.8,3000.7 ; 6876.9,3000.4 6884.5,3001.1 6892,3002.4 6899.3,3004.5 6906.5,3007.3 6913.3,3010.8 6919.7,3014.9 6925.7,3019.6 6931.2,3024.8 6936.2,3030.6 6940.6,3036.8 6944.5,3043.4 6947.6,3050.4 6950.1,3057.6 6951.8,3065 6952.8,3072.6 6953.1,3080.2 ; 6948.8,4417 6952.4,3080.6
